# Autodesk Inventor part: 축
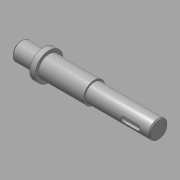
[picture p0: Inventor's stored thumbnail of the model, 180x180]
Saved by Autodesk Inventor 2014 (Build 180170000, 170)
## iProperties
Created: 2015-09
Part Number: 축
Material: 강철, 연강
Document SubType Name: Modeling
Designer: mduedu
Density: 7.86 g/cm^3
Mass: 263.424 g
Surface Area: 86.4309 cm^2
Volume: 33.5145 cm^3
Appearance: 강철
Author: mduedu
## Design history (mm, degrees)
sketch "스케치1"
  geometry: L1 (-64, 0)-(64, 0); L2 (-64, 0)-(-64, 8.5); L3 (-64, 8.5)-(-43, 8.5); L4 (-43, 8.5)-(-43, 13); L5 (-43, 13)-(-38, 13); L6 (-38, 13)-(-38, 10); L7 (-38, 10)-(4, 10); L8 (4, 10)-(4, 8.5); L9 (4, 8.5)-(64, 8.5); L10 (64, 8.5)-(64, 0); 2 further points
  constraints: 20 end point, 5 parallel, 2 horizontal, 2 perpendicular, 1 coincident, 1 midpoint, 1 vertical
  dimensions: "d0" = 128 distance of L1.start L1.end; "d2" = 5 distance of L4.end L5.end; "d3" = 42 distance of L6.end L7.end; "d4" = 60 distance of L8.end L9.end; "d5" = 17 diameter of L3 L1; "d6" = 17 diameter of L9 L1; "d7" = 20 diameter of L7 L1; "d8" = 26 diameter of L5 L1
revolve "회전1" sketch "스케치1" stored, may be unused: angle "d9" = 90 deg
node "작업 평면1"
sketch "스케치2"
  geometry: L1 (5.5, 2.5)-(18.5, 2.5); L2 (18.5, -2.5)-(5.5, -2.5); L3 (5.5, 2.5)-(18.5, -2.5); L4 (18.5, 2.5)-(5.5, -2.5); L5 (30, -8.5)-(30, 8.5) reference; A1 r 2.5 centre (5.5, 0) between (5.5, 2.5) and (5.5, -2.5); A2 r 2.5 centre (18.5, 0) between (18.5, -2.5) and (18.5, 2.5); 2 further points
  constraints: 8 end point, 4 point on circle, 4 tangent, 2 centre point, 2 midpoint, 1 horizontal, 1 horizontal alignment, 1 parallel
  dimensions: "d10" = 18 dimension on A2 A1; "d12" = 9 distance edge to line of A2 L5; "d13" = 5 distance between parallel lines of L2 L1
extrude "돌출1" cut sketch "스케치2" distance "d14" = 3; taper "d15" = 0 deg
node "작업 평면2"
sketch "스케치4"
  geometry: L1 (7, -3)-(-9, -3); L2 (-9, 3)-(7, 3); L3 (-21, 10)-(-21, -10) reference; A1 r 3 centre (-9, 0) between (-9, 3) and (-9, -3); A2 r 3 centre (7, 0) between (7, -3) and (7, 3); 1 further point
  constraints: 4 end point, 4 point on circle, 4 tangent, 2 centre point, 1 horizontal, 1 horizontal alignment, 1 parallel
  dimensions: "d16" = 22 dimension on A1 A2; "d18" = 6 distance between parallel lines of L2 L1; "d19" = 9 distance edge to line of A1 L3
extrude "돌출2" cut sketch "스케치4" distance "d20" = 3.5; taper "d21" = 0 deg
sketch "스케치5"
  geometry: L1 (4, 8.5)-(64, 8.5) reference; L2 (4, -8.5)-(64, -8.5) reference; L3 (37, 8.5)-(37, -8.5); L4 (37, -6.5)-(35, -8.5); L5 (37, -8.5)-(35, -8.5); L6 (37, -8.5)-(37, -6.5); L7 (4, -10)-(4, 10) reference; 1 further point
  constraints: 8 end point, 4 point on line, 1 collinear, 1 perpendicular
  dimensions: "d22" = 4 diameter of L4.end L3; "d24" = 45 deg angle of L3 L4; "d26" = 33 distance between parallel lines of L3 L7
revolve "회전2" sketch "스케치5" stored, may be unused: angle "d27" = 90 deg
chamfer "모따기1" distance "d28" = 1; stored, may be unused: second distance "d29" = 2, angle "d30" = 45 deg
sketch "스케치6"
  geometry: L1 (37, -6.5)-(35, -8.5) reference; L2 (37, -6.5)-(39, -8.5) reference; 2 further points
  constraints: 1 coincident
node "솔리드1"
